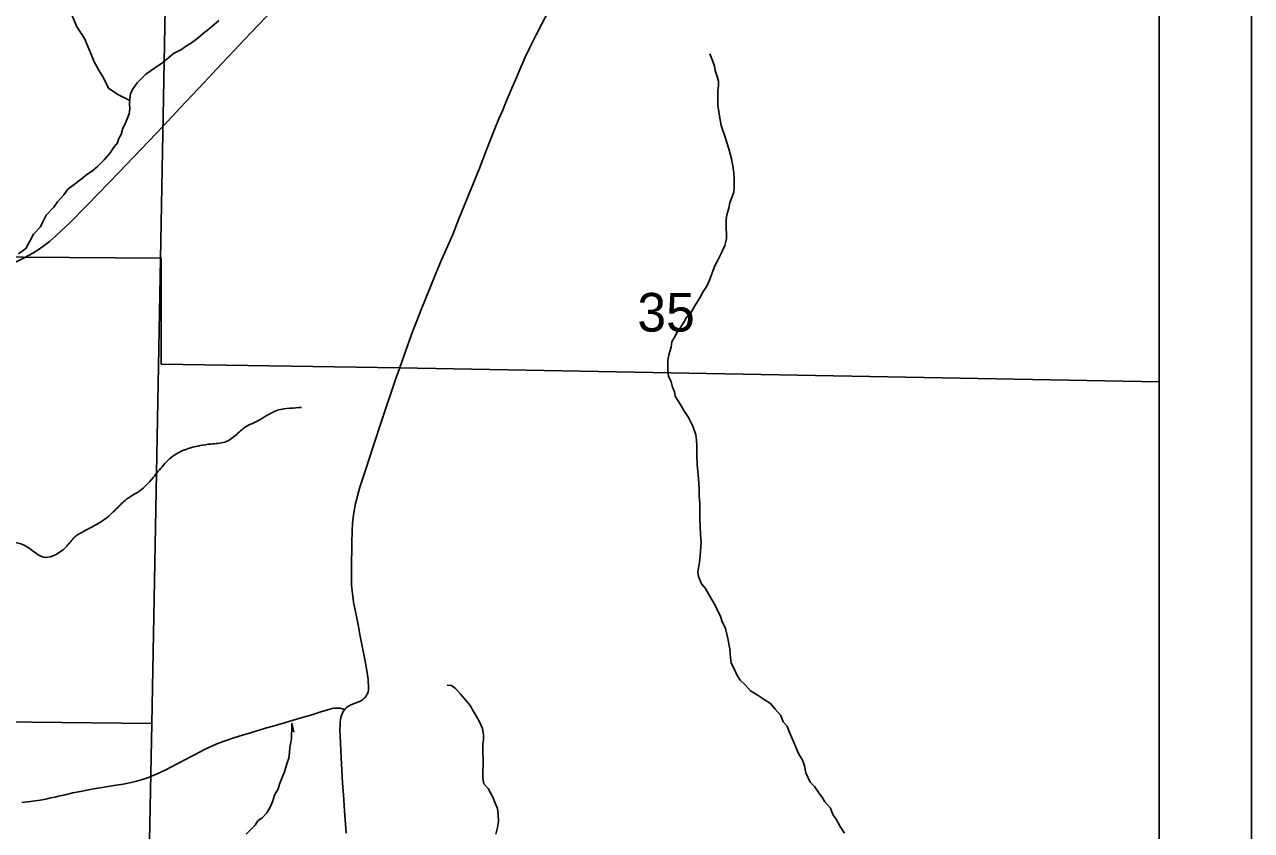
# Model space of a CAD drawing. Extents: x 0 to 34, y 0 to 22.
# Drawn here: x 24.17 to 25.5, y 18.521 to 19.394 of the extents above; entities that cross this region are included whole.
import ezdxf

# ---------------------------------------------------------------- set-up
doc = ezdxf.new("R2010")
doc.units = 0
for name, color, linetype in [('GM_X_Corporation', 7, 'Continuous'), ('GM_X_Minor_River', 7, 'Continuous'), ('GM_X_Section_Text', 7, 'Continuous'), ('GM_X_State_Route', 7, 'Continuous'), ('GM_X_Township_Road', 7, 'Continuous'), ('SH_Data', 7, 'Continuous')]:
    doc.layers.add(name, color=color, linetype=linetype)

msp = doc.modelspace()

# ---------------------------------------------------------------- linework, layer by layer
at = {"layer": 'GM_X_Corporation'}
for points in [[(25.4, 19.0068), (25.4, 20.4), (21.2921, 20.4), (21.2757, 19.6748), (21.2742, 19.6071), (21.273, 19.5535), (21.2652, 19.1913), (21.5297, 19.1865), (21.7744, 19.1817), (21.8956, 19.1793), (22.6423, 19.1645), (23.3329, 19.1508), (23.5499, 19.1465), (23.786, 19.1434), (24.169, 19.1418), (24.3186, 19.1409), (24.3186, 19.0261), (24.5766, 19.0222)], [(23.3052, 19.6529), (24.3281, 19.637), (24.3248, 19.5084), (24.3084, 18.6368), (23.3004, 18.648)], [(25.4, 18.4978), (25.4, 19.5078), (24.3248, 19.5084), (24.3084, 18.6368), (24.3059, 18.5094)], [(23.3004, 18.648), (24.3084, 18.6368), (24.3059, 18.5094), (24.2773, 17.6357), (23.2763, 17.6399)]]:
    msp.add_lwpolyline(points, close=True, dxfattribs=at)
msp.add_lwpolyline([(25.4, 14.4307), (25.4, 19.0068), (24.5766, 19.0222), (24.3186, 19.0261), (24.3186, 19.1409), (24.169, 19.1418), (23.786, 19.1434), (23.5499, 19.1465), (23.3329, 19.1508), (22.6423, 19.1645), (21.8956, 19.1793), (21.7744, 19.1817), (21.5297, 19.1865), (21.2652, 19.1913), (20.8916, 19.1966), (20.254, 19.2058), (20.2471, 18.8539), (20.2208, 16.9558), (20.1987, 15.2691)], dxfattribs=at)
at = {"layer": 'GM_X_Minor_River'}
for points in [[(24.2844, 19.3117), (24.2716, 19.3182), (24.2613, 19.325), (24.2559, 19.336), (24.2514, 19.3436), (24.246, 19.3535), (24.2437, 19.3588), (24.2395, 19.3694), (24.2353, 19.3789), (24.2269, 19.3922), (24.2219, 19.4036)], [(24.164, 19.1456), (24.1719, 19.1513), (24.1761, 19.1593), (24.1802, 19.1669), (24.1878, 19.1749), (24.1904, 19.1802), (24.1938, 19.1874), (24.2021, 19.1962), (24.2063, 19.2019), (24.2131, 19.2095), (24.2173, 19.2156), (24.2226, 19.2194), (24.2275, 19.2232), (24.2335, 19.2278), (24.2381, 19.2316), (24.2442, 19.2354), (24.2495, 19.24), (24.2566, 19.2472), (24.2634, 19.2552), (24.2665, 19.2601), (24.271, 19.2658), (24.2725, 19.2704), (24.2751, 19.2749), (24.277, 19.2818), (24.2793, 19.2863), (24.2838, 19.297), (24.2845, 19.3027), (24.2841, 19.3076), (24.2845, 19.3133), (24.2852, 19.319), (24.2875, 19.3236), (24.2924, 19.3308), (24.3019, 19.3403), (24.3113, 19.3468), (24.3193, 19.3521), (24.3265, 19.3578), (24.3318, 19.3624), (24.3405, 19.367), (24.345, 19.37), (24.3515, 19.3742), (24.3568, 19.378), (24.364, 19.3841), (24.3704, 19.3894), (24.381, 19.3982)], [(24.9131, 19.362), (24.9161, 19.3548), (24.918, 19.3487), (24.9188, 19.3441), (24.9211, 19.3377), (24.9223, 19.3324), (24.9223, 19.3274), (24.9219, 19.3229), (24.9219, 19.3164), (24.9216, 19.3065), (24.9232, 19.2967), (24.9255, 19.2845), (24.9297, 19.272), (24.9335, 19.2591), (24.9366, 19.2485), (24.9382, 19.2386), (24.9389, 19.2329), (24.9393, 19.2272), (24.9394, 19.2173), (24.939, 19.2124), (24.9349, 19.2006), (24.9338, 19.1949), (24.9315, 19.1877), (24.9308, 19.1828), (24.9308, 19.1725), (24.9312, 19.168), (24.9312, 19.1619), (24.9293, 19.1547), (24.9252, 19.1459), (24.9214, 19.1379), (24.9184, 19.1326), (24.9165, 19.1277), (24.915, 19.1227), (24.9128, 19.117), (24.9098, 19.1106), (24.9056, 19.1041), (24.9022, 19.098), (24.8969, 19.0893), (24.8924, 19.0817), (24.8882, 19.0771), (24.8848, 19.0714), (24.8807, 19.0646), (24.8773, 19.06), (24.8743, 19.0547), (24.872, 19.0501), (24.8713, 19.0444), (24.869, 19.0372), (24.8675, 19.0304), (24.8676, 19.0186), (24.8683, 19.0129), (24.871, 19.0068), (24.8726, 19.0011), (24.8749, 18.9962), (24.8756, 18.9913), (24.8787, 18.9863), (24.8821, 18.981), (24.8848, 18.9757), (24.8901, 18.9681), (24.8947, 18.9587), (24.8978, 18.9495), (24.8986, 18.9435), (24.899, 18.9374), (24.899, 18.9271), (24.8994, 18.9173), (24.9002, 18.9097), (24.9006, 18.9017), (24.9014, 18.8915), (24.9014, 18.8827), (24.9022, 18.8759), (24.9023, 18.8573), (24.9027, 18.8512), (24.9031, 18.8413), (24.9035, 18.833), (24.9032, 18.828), (24.9028, 18.8235), (24.9024, 18.8182), (24.9017, 18.8117), (24.9002, 18.8007), (24.9006, 18.7961), (24.9041, 18.7882), (24.9083, 18.7829), (24.9121, 18.7764), (24.9155, 18.7703), (24.9193, 18.7643), (24.9216, 18.7586), (24.9247, 18.7529), (24.9262, 18.748), (24.93, 18.7396), (24.9327, 18.729), (24.9347, 18.7176), (24.9351, 18.7127), (24.9355, 18.7081), (24.9362, 18.702), (24.9397, 18.6952), (24.9424, 18.6895), (24.9458, 18.6838), (24.9515, 18.6785), (24.9572, 18.6721), (24.9645, 18.6679), (24.9721, 18.6626), (24.9789, 18.6584)], [(24.681, 18.517), (24.6829, 18.5242), (24.684, 18.5307), (24.6836, 18.5383), (24.6828, 18.5447), (24.6805, 18.5504), (24.6778, 18.5569), (24.6729, 18.5663), (24.6683, 18.5713), (24.6671, 18.5777), (24.6671, 18.583), (24.6675, 18.5929), (24.6674, 18.5994), (24.667, 18.6043), (24.667, 18.6142), (24.6677, 18.6191), (24.6677, 18.6244), (24.6666, 18.6313), (24.6639, 18.6377), (24.6612, 18.6426), (24.6566, 18.6506), (24.6532, 18.6563), (24.6478, 18.6627), (24.6429, 18.6684), (24.6376, 18.6745), (24.633, 18.6779), (24.6284, 18.6783)], [(24.9789, 18.6584), (24.9839, 18.6524), (24.99, 18.6455), (24.9927, 18.6387), (24.9969, 18.6338), (24.9988, 18.6288), (25.0034, 18.6178), (25.0091, 18.6042), (25.0133, 18.597), (25.0156, 18.5909), (25.0172, 18.5833), (25.0217, 18.5731), (25.0263, 18.5685), (25.0313, 18.5617), (25.0351, 18.5564), (25.0378, 18.5518), (25.0439, 18.545), (25.0465, 18.5382), (25.0504, 18.5325), (25.0542, 18.5253), (25.0591, 18.5181)], [(24.4107, 18.5169), (24.4205, 18.5267), (24.4232, 18.5313), (24.4281, 18.5347), (24.433, 18.5401), (24.4364, 18.5454), (24.439, 18.5518), (24.4413, 18.5591), (24.4451, 18.5659), (24.4466, 18.5712), (24.4496, 18.5781), (24.4522, 18.5845), (24.4537, 18.5895), (24.4552, 18.594), (24.4567, 18.5993), (24.4575, 18.6054), (24.4578, 18.6107), (24.4589, 18.6161), (24.4597, 18.6206), (24.4597, 18.6252), (24.46, 18.6297), (24.46, 18.637), (24.4623, 18.6275)]]:
    msp.add_lwpolyline(points, dxfattribs=at)
msp.add_spline([(23.9568, 19.01), (23.9772, 18.9906), (23.9888, 18.9794), (23.9992, 18.9716), (24.0088, 18.9683), (24.0217, 18.9666), (24.0328, 18.9623), (24.0432, 18.9552), (24.0537, 18.9444), (24.063, 18.9343), (24.0697, 18.9245), (24.0767, 18.9117), (24.0819, 18.9), (24.089, 18.8883), (24.0995, 18.8748), (24.1099, 18.864), (24.1219, 18.8547), (24.1346, 18.8435), (24.1443, 18.8372), (24.1546, 18.8336), (24.1664, 18.8315), (24.1807, 18.8226), (24.1929, 18.8167), (24.2039, 18.8196), (24.2163, 18.8289), (24.2249, 18.8389), (24.235, 18.8452), (24.2501, 18.8534), (24.2599, 18.86), (24.273, 18.8724), (24.2838, 18.8817), (24.2948, 18.8884), (24.3097, 18.9031), (24.3209, 18.9166), (24.3351, 18.929), (24.3514, 18.9357), (24.3608, 18.9378), (24.3722, 18.9395), (24.3874, 18.9416), (24.3994, 18.9491), (24.4099, 18.958), (24.4209, 18.9635), (24.4306, 18.969), (24.4446, 18.976), (24.4583, 18.9782), (24.4704, 18.9791)], degree=3, dxfattribs=at)
at = {"layer": 'GM_X_State_Route'}
msp.add_lwpolyline([(24.1437, 19.1295), (24.16, 19.1362), (24.1679, 19.1401), (24.1746, 19.1436), (24.1795, 19.1464), (24.1861, 19.1506), (24.1918, 19.1546), (24.1975, 19.1589), (24.2039, 19.1645), (24.2108, 19.171), (24.2183, 19.1782), (24.239, 19.1991), (24.2726, 19.2337), (24.2884, 19.2502), (24.313, 19.2758), (24.3256, 19.2893), (24.3395, 19.3041), (24.3518, 19.3171), (24.3652, 19.3312), (24.3784, 19.3454), (24.3912, 19.3589), (24.4157, 19.3849), (24.4409, 19.4114)], dxfattribs=at)
at = {"layer": 'GM_X_Township_Road'}
msp.add_line((24.5744, 19.0146), (24.575, 19.0164), dxfattribs=at)
for points in [[(24.575, 19.0164), (24.5816, 19.0347), (24.5913, 19.0622), (24.5954, 19.0731), (24.6, 19.0842), (24.6155, 19.1225), (24.6223, 19.1391), (24.6287, 19.1534), (24.6344, 19.1666), (24.641, 19.1836), (24.663, 19.2374), (24.6709, 19.2581), (24.6797, 19.2802), (24.6845, 19.2919), (24.6882, 19.3003), (24.6917, 19.3086), (24.6975, 19.3224), (24.7034, 19.3364), (24.7074, 19.3459), (24.713, 19.3586), (24.7179, 19.369), (24.7247, 19.3827), (24.7306, 19.3938), (24.7463, 19.4241)], [(24.517, 18.6517), (24.5178, 18.6527), (24.5188, 18.6536), (24.5206, 18.655), (24.5221, 18.656), (24.5241, 18.6569), (24.5334, 18.6606), (24.5348, 18.6614), (24.5366, 18.6624), (24.5382, 18.6637), (24.5398, 18.6654), (24.5411, 18.6674), (24.5419, 18.6689), (24.5427, 18.6712), (24.5431, 18.6734), (24.5433, 18.6758), (24.5428, 18.6839), (24.5419, 18.69), (24.5394, 18.7042), (24.5355, 18.7243), (24.5339, 18.7331), (24.5322, 18.742), (24.5293, 18.7564), (24.5272, 18.7665), (24.5269, 18.7684), (24.5252, 18.7833), (24.5249, 18.7867), (24.5247, 18.7982), (24.5249, 18.8048), (24.5252, 18.8326), (24.5255, 18.8453), (24.5259, 18.8533), (24.5266, 18.86), (24.5273, 18.8648), (24.5292, 18.875), (24.5301, 18.879), (24.5328, 18.8888), (24.5342, 18.8938), (24.5402, 18.9124), (24.5438, 18.9233), (24.5489, 18.9389), (24.5572, 18.9641), (24.574, 19.0137), (24.5744, 19.0146)], [(24.1675, 18.551), (24.1767, 18.5522), (24.1819, 18.5529), (24.1874, 18.5538), (24.1934, 18.5549), (24.1987, 18.5561), (24.2036, 18.5571), (24.2073, 18.5579), (24.2144, 18.5596), (24.2228, 18.5615), (24.2309, 18.5632), (24.2398, 18.5649), (24.2477, 18.5662), (24.2566, 18.5677), (24.2671, 18.5695), (24.2773, 18.5712), (24.286, 18.573), (24.2916, 18.5742), (24.2957, 18.5752), (24.3004, 18.5767), (24.3047, 18.5783), (24.3079, 18.5797), (24.3106, 18.5807), (24.3133, 18.582), (24.3241, 18.5871), (24.3281, 18.5892), (24.3613, 18.6066), (24.3654, 18.6086), (24.3748, 18.6131), (24.3807, 18.6155), (24.3877, 18.618), (24.3952, 18.6206), (24.4031, 18.6231), (24.4162, 18.6271), (24.4245, 18.6297), (24.4317, 18.6318), (24.4409, 18.6344), (24.452, 18.6376), (24.4614, 18.6403), (24.4729, 18.6437), (24.4816, 18.6463), (24.4916, 18.6493), (24.5013, 18.6523), (24.5039, 18.6529), (24.5063, 18.6533), (24.5085, 18.6535), (24.5125, 18.6532), (24.5145, 18.6528), (24.5161, 18.6522), (24.517, 18.6517)], [(24.5191, 18.5178), (24.5171, 18.5422), (24.5159, 18.5594), (24.5151, 18.5723), (24.5142, 18.5861), (24.5134, 18.6), (24.5123, 18.6233), (24.5122, 18.6293), (24.5123, 18.6362), (24.5124, 18.6384), (24.5127, 18.6407), (24.5132, 18.6432), (24.5138, 18.6454), (24.5152, 18.6489), (24.5159, 18.6501), (24.517, 18.6517)]]:
    msp.add_lwpolyline(points, dxfattribs=at)
at = {"layer": 'SH_Data'}
for points in [[(18.5, 20.5), (25.5, 20.5), (25.5, 13.5), (18.5, 13.5)], [(18.6, 20.4), (25.4, 20.4), (25.4, 13.6), (18.6, 13.6)]]:
    msp.add_lwpolyline(points, close=True, dxfattribs=at)

# ---------------------------------------------------------------- texts
at = {"layer": 'GM_X_Section_Text'}
msp.add_text('35', height=0.04186, rotation=0, dxfattribs=at).set_placement((24.8345, 19.0613))

doc.saveas('drawing.dxf')
